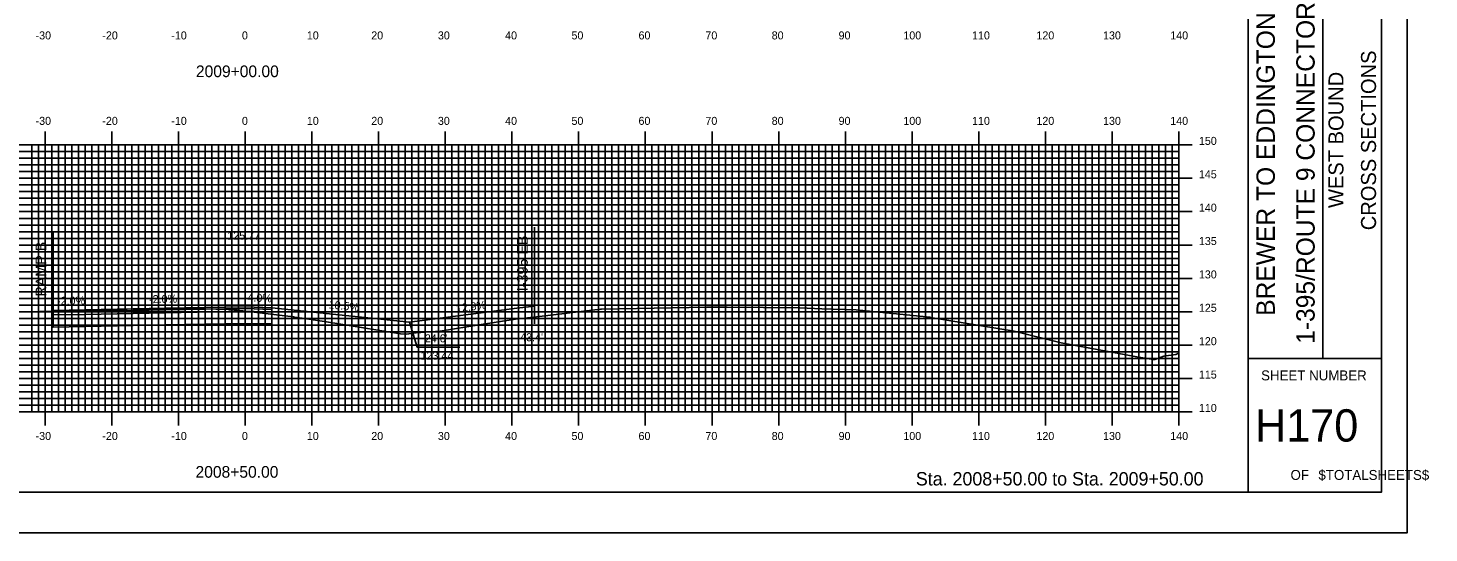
# Model space of a CAD drawing. Extents: x 853107 to 853450, y 366605 to 366825.
# Drawn here: x 853239.9 to 853450, y 366604.9 to 366680.6 of the extents above; entities that cross this region are included whole.
import ezdxf

# ---------------------------------------------------------------- set-up
doc = ezdxf.new("R2010")
doc.units = 0
for name, color, linetype in [('ANNOTATION', 7, 'Continuous'), ('BORDER', 7, 'Continuous'), ('D_Drainage_Underdrain', 7, 'Continuous'), ('D_Roadway_Centerline', 7, 'Continuous'), ('D_Roadway_Centerline_Text', 7, 'Continuous'), ('D_Roadway_Edge_Shoulder', 7, 'Continuous'), ('D_Roadway_Edge_TW', 7, 'Continuous'), ('D_Roadway_Pavement', 7, 'Continuous'), ('D_Roadway_SubGrade', 7, 'Continuous'), ('D_Text_Standard', 7, 'Continuous'), ('H_V ANNOTATION', 7, 'Continuous'), ('JUNK', 7, 'Continuous'), ('M_Roadway_Centerline', 7, 'Continuous'), ('MAJOR', 7, 'Continuous'), ('MINOR', 7, 'Continuous'), ('PLOT BOUNDARY', 7, 'Continuous'), ('S_Roadway_Centerline', 7, 'Continuous')]:
    doc.layers.add(name, color=color, linetype=linetype)

msp = doc.modelspace()

# ---------------------------------------------------------------- linework, layer by layer
at = {"layer": 'ANNOTATION'}
msp.add_lwpolyline([(853304.67, 366632.77), (853298.27, 366632.77), (853297.13, 366636.5)], dxfattribs=at)
at = {"layer": 'BORDER'}
for p, q in [((853422.9, 366611.06), (853422.9, 366821.06)), ((853434.09, 366631.06), (853434.09, 366701.06)), ((853422.9, 366631.06), (853442.9, 366631.06))]:
    msp.add_line(p, q, dxfattribs=at)
msp.add_lwpolyline([(853122.9, 366611.06), (853442.9, 366611.06), (853442.9, 366821.06), (853122.9, 366821.06)], close=True, dxfattribs=at)
at = {"layer": 'D_Drainage_Underdrain'}
msp.add_lwpolyline([(853243.7, 366638.25), (853243.7, 366635.75), (853248.5, 366635.85)], dxfattribs=at)
at = {"layer": 'D_Roadway_Centerline'}
for points in [[(853243.7, 366638.25), (853243.7, 366638.25), (853246.71, 366638.31), (853248.5, 366638.35), (853248.5, 366638.35), (853248.51, 366638.35), (853260.5, 366638.59), (853272.5, 366638.83), (853276.5, 366638.67), (853276.5, 366638.67), (853297.12, 366636.5), (853297.13, 366636.5)], [(853276.5, 366638.67), (853297.13, 366636.5)], [(853297.13, 366636.5), (853313.26, 366638.59), (853315.88, 366638.93)]]:
    msp.add_lwpolyline(points, dxfattribs=at)
at = {"layer": 'D_Roadway_Edge_Shoulder'}
msp.add_lwpolyline([(853272.5, 366638.83), (853276.5, 366638.67), (853276.5, 366638.42), (853272.5, 366638.58)], close=True, dxfattribs=at)
at = {"layer": 'D_Roadway_Edge_TW'}
for points in [[(853272.5, 366638.83), (853260.5, 366638.59), (853260.5, 366638.34), (853272.5, 366638.58)], [(853248.5, 366638.35), (853243.7, 366638.25), (853243.7, 366638), (853248.5, 366638.1)], [(853260.5, 366638.59), (853248.5, 366638.35), (853248.5, 366638.1), (853260.5, 366638.34)]]:
    msp.add_lwpolyline(points, close=True, dxfattribs=at)
at = {"layer": 'D_Roadway_Pavement'}
for points in [[(853248.5, 366638.1), (853243.7, 366638), (853243.7, 366637.59), (853248.5, 366637.68)], [(853260.5, 366638.34), (853248.5, 366638.1), (853248.5, 366637.68), (853260.5, 366637.92)], [(853272.5, 366638.58), (853260.5, 366638.34), (853260.5, 366637.92), (853272.5, 366638.16)], [(853272.5, 366638.58), (853276.5, 366638.42), (853276.5, 366638), (853272.5, 366638.16)]]:
    msp.add_lwpolyline(points, close=True, dxfattribs=at)
msp.add_lwpolyline([(853260.5, 366638.34), (853260.5, 366637.92)], dxfattribs=at)
at = {"layer": 'D_Roadway_SubGrade'}
for p, q in [((853243.7, 366650.06), (853243.7, 366635.75)), ((853315.88, 366650.73), (853315.88, 366638.93))]:
    msp.add_line(p, q, dxfattribs=at)
for points in [[(853272.5, 366638.16), (853276.5, 366638), (853276.5, 366638.42), (853276.5, 366638.67), (853276.5, 366636.25), (853272.5, 366636.33)], [(853248.5, 366637.68), (853243.7, 366637.59), (853243.7, 366637.59), (853243.7, 366635.75), (853248.5, 366635.85)], [(853260.5, 366637.92), (853248.5, 366637.68), (853248.5, 366635.85), (853260.5, 366636.09)], [(853272.5, 366638.16), (853260.5, 366637.92), (853260.5, 366636.09), (853272.5, 366636.33)]]:
    msp.add_lwpolyline(points, close=True, dxfattribs=at)
at = {"layer": 'JUNK'}
msp.add_line((853315.88, 366638.93), (853315.88, 366636.25), dxfattribs=at)
at = {"layer": 'MAJOR'}
for p, q in [((853242.5, 366665.06), (853242.5, 366663.06)), ((853252.5, 366665.06), (853252.5, 366663.06)), ((853262.5, 366665.06), (853262.5, 366663.06)), ((853272.5, 366665.06), (853272.5, 366663.06)), ((853282.5, 366665.06), (853282.5, 366663.06)), ((853292.5, 366665.06), (853292.5, 366663.06)), ((853302.5, 366665.06), (853302.5, 366663.06)), ((853312.5, 366665.06), (853312.5, 366663.06)), ((853322.5, 366665.06), (853322.5, 366663.06)), ((853332.5, 366665.06), (853332.5, 366663.06)), ((853342.5, 366665.06), (853342.5, 366663.06)), ((853352.5, 366665.06), (853352.5, 366663.06)), ((853362.5, 366665.06), (853362.5, 366663.06)), ((853372.5, 366665.06), (853372.5, 366663.06)), ((853382.5, 366665.06), (853382.5, 366663.06)), ((853392.5, 366665.06), (853392.5, 366663.06)), ((853402.5, 366665.06), (853402.5, 366663.06)), ((853412.5, 366665.06), (853412.5, 366663.06)), ((853132.5, 366663.06), (853412.5, 366663.06)), ((853132.5, 366663.06), (853412.5, 366663.06)), ((853242.5, 366623.06), (853242.5, 366663.06)), ((853252.5, 366623.06), (853252.5, 366663.06)), ((853262.5, 366623.06), (853262.5, 366663.06)), ((853272.5, 366623.06), (853272.5, 366663.06)), ((853282.5, 366623.06), (853282.5, 366663.06)), ((853292.5, 366623.06), (853292.5, 366663.06)), ((853302.5, 366623.06), (853302.5, 366663.06)), ((853312.5, 366623.06), (853312.5, 366663.06)), ((853322.5, 366623.06), (853322.5, 366663.06)), ((853332.5, 366623.06), (853332.5, 366663.06)), ((853342.5, 366623.06), (853342.5, 366663.06)), ((853352.5, 366623.06), (853352.5, 366663.06)), ((853362.5, 366623.06), (853362.5, 366663.06)), ((853372.5, 366623.06), (853372.5, 366663.06)), ((853382.5, 366623.06), (853382.5, 366663.06)), ((853392.5, 366623.06), (853392.5, 366663.06)), ((853402.5, 366623.06), (853402.5, 366663.06)), ((853414.51, 366663.06), (853410.5, 366663.06)), ((853412.5, 366623.06), (853412.5, 366663.06)), ((853412.5, 366623.06), (853412.5, 366663.06)), ((853132.5, 366658.06), (853412.5, 366658.06)), ((853414.51, 366658.06), (853410.5, 366658.06)), ((853132.5, 366653.06), (853412.5, 366653.06)), ((853414.51, 366653.06), (853410.5, 366653.06)), ((853132.5, 366648.06), (853412.5, 366648.06)), ((853414.51, 366648.06), (853410.5, 366648.06)), ((853132.5, 366643.06), (853412.5, 366643.06)), ((853414.51, 366643.06), (853410.5, 366643.06)), ((853132.5, 366638.06), (853412.5, 366638.06)), ((853414.51, 366638.06), (853410.5, 366638.06)), ((853132.5, 366633.06), (853412.5, 366633.06)), ((853414.51, 366633.06), (853410.5, 366633.06)), ((853132.5, 366628.06), (853412.5, 366628.06)), ((853414.51, 366628.06), (853410.5, 366628.06)), ((853132.5, 366623.06), (853412.5, 366623.06)), ((853132.5, 366623.06), (853412.5, 366623.06)), ((853242.5, 366621.05), (853242.5, 366623.06)), ((853252.5, 366621.05), (853252.5, 366623.06)), ((853262.5, 366621.05), (853262.5, 366623.06)), ((853272.5, 366621.05), (853272.5, 366623.06)), ((853282.5, 366621.05), (853282.5, 366623.06)), ((853292.5, 366621.05), (853292.5, 366623.06)), ((853302.5, 366621.05), (853302.5, 366623.06)), ((853312.5, 366621.05), (853312.5, 366623.06)), ((853322.5, 366621.05), (853322.5, 366623.06)), ((853332.5, 366621.05), (853332.5, 366623.06)), ((853342.5, 366621.05), (853342.5, 366623.06)), ((853352.5, 366621.05), (853352.5, 366623.06)), ((853362.5, 366621.05), (853362.5, 366623.06)), ((853372.5, 366621.05), (853372.5, 366623.06)), ((853382.5, 366621.05), (853382.5, 366623.06)), ((853392.5, 366621.05), (853392.5, 366623.06)), ((853402.5, 366621.05), (853402.5, 366623.06)), ((853414.51, 366623.06), (853410.5, 366623.06)), ((853412.5, 366621.05), (853412.5, 366623.06))]:
    msp.add_line(p, q, dxfattribs=at)
at = {"layer": 'MINOR'}
for p, q in [((853132.5, 366662.06), (853412.5, 366662.06)), ((853240.5, 366623.06), (853240.5, 366663.06)), ((853241.5, 366623.06), (853241.5, 366663.06)), ((853243.5, 366623.06), (853243.5, 366663.06)), ((853244.5, 366623.06), (853244.5, 366663.06)), ((853245.5, 366623.06), (853245.5, 366663.06)), ((853246.5, 366623.06), (853246.5, 366663.06)), ((853247.5, 366623.06), (853247.5, 366663.06)), ((853248.5, 366623.06), (853248.5, 366663.06)), ((853249.5, 366623.06), (853249.5, 366663.06)), ((853250.5, 366623.06), (853250.5, 366663.06)), ((853251.5, 366623.06), (853251.5, 366663.06)), ((853253.5, 366623.06), (853253.5, 366663.06)), ((853254.5, 366623.06), (853254.5, 366663.06)), ((853255.5, 366623.06), (853255.5, 366663.06)), ((853256.5, 366623.06), (853256.5, 366663.06)), ((853257.5, 366623.06), (853257.5, 366663.06)), ((853258.5, 366623.06), (853258.5, 366663.06)), ((853259.5, 366623.06), (853259.5, 366663.06)), ((853260.5, 366623.06), (853260.5, 366663.06)), ((853261.5, 366623.06), (853261.5, 366663.06)), ((853263.5, 366623.06), (853263.5, 366663.06)), ((853264.5, 366623.06), (853264.5, 366663.06)), ((853265.5, 366623.06), (853265.5, 366663.06)), ((853266.5, 366623.06), (853266.5, 366663.06)), ((853267.5, 366623.06), (853267.5, 366663.06)), ((853268.5, 366623.06), (853268.5, 366663.06)), ((853269.5, 366623.06), (853269.5, 366663.06)), ((853270.5, 366623.06), (853270.5, 366663.06)), ((853271.5, 366623.06), (853271.5, 366663.06)), ((853273.5, 366623.06), (853273.5, 366663.06)), ((853274.5, 366623.06), (853274.5, 366663.06)), ((853275.5, 366623.06), (853275.5, 366663.06)), ((853276.5, 366623.06), (853276.5, 366663.06)), ((853277.5, 366623.06), (853277.5, 366663.06)), ((853278.5, 366623.06), (853278.5, 366663.06)), ((853279.5, 366623.06), (853279.5, 366663.06)), ((853280.5, 366623.06), (853280.5, 366663.06)), ((853281.5, 366623.06), (853281.5, 366663.06)), ((853283.5, 366623.06), (853283.5, 366663.06)), ((853284.5, 366623.06), (853284.5, 366663.06)), ((853285.5, 366623.06), (853285.5, 366663.06)), ((853286.5, 366623.06), (853286.5, 366663.06)), ((853287.5, 366623.06), (853287.5, 366663.06)), ((853288.5, 366623.06), (853288.5, 366663.06)), ((853289.5, 366623.06), (853289.5, 366663.06)), ((853290.5, 366623.06), (853290.5, 366663.06)), ((853291.5, 366623.06), (853291.5, 366663.06)), ((853293.5, 366623.06), (853293.5, 366663.06)), ((853294.5, 366623.06), (853294.5, 366663.06)), ((853295.5, 366623.06), (853295.5, 366663.06)), ((853296.5, 366623.06), (853296.5, 366663.06)), ((853297.5, 366623.06), (853297.5, 366663.06)), ((853298.5, 366623.06), (853298.5, 366663.06)), ((853299.5, 366623.06), (853299.5, 366663.06)), ((853300.5, 366623.06), (853300.5, 366663.06)), ((853301.5, 366623.06), (853301.5, 366663.06)), ((853303.5, 366623.06), (853303.5, 366663.06)), ((853304.5, 366623.06), (853304.5, 366663.06)), ((853305.5, 366623.06), (853305.5, 366663.06)), ((853306.5, 366623.06), (853306.5, 366663.06)), ((853307.5, 366623.06), (853307.5, 366663.06)), ((853308.5, 366623.06), (853308.5, 366663.06)), ((853309.5, 366623.06), (853309.5, 366663.06)), ((853310.5, 366623.06), (853310.5, 366663.06)), ((853311.5, 366623.06), (853311.5, 366663.06)), ((853313.5, 366623.06), (853313.5, 366663.06)), ((853314.5, 366623.06), (853314.5, 366663.06)), ((853315.5, 366623.06), (853315.5, 366663.06)), ((853316.5, 366623.06), (853316.5, 366663.06)), ((853317.5, 366623.06), (853317.5, 366663.06)), ((853318.5, 366623.06), (853318.5, 366663.06)), ((853319.5, 366623.06), (853319.5, 366663.06)), ((853320.5, 366623.06), (853320.5, 366663.06)), ((853321.5, 366623.06), (853321.5, 366663.06)), ((853323.5, 366623.06), (853323.5, 366663.06)), ((853324.5, 366623.06), (853324.5, 366663.06)), ((853325.5, 366623.06), (853325.5, 366663.06)), ((853326.5, 366623.06), (853326.5, 366663.06)), ((853327.5, 366623.06), (853327.5, 366663.06)), ((853328.5, 366623.06), (853328.5, 366663.06)), ((853329.5, 366623.06), (853329.5, 366663.06)), ((853330.5, 366623.06), (853330.5, 366663.06)), ((853331.5, 366623.06), (853331.5, 366663.06)), ((853333.5, 366623.06), (853333.5, 366663.06)), ((853334.5, 366623.06), (853334.5, 366663.06)), ((853335.5, 366623.06), (853335.5, 366663.06)), ((853336.5, 366623.06), (853336.5, 366663.06)), ((853337.5, 366623.06), (853337.5, 366663.06)), ((853338.5, 366623.06), (853338.5, 366663.06)), ((853339.5, 366623.06), (853339.5, 366663.06)), ((853340.5, 366623.06), (853340.5, 366663.06)), ((853341.5, 366623.06), (853341.5, 366663.06)), ((853343.5, 366623.06), (853343.5, 366663.06)), ((853344.5, 366623.06), (853344.5, 366663.06)), ((853345.5, 366623.06), (853345.5, 366663.06)), ((853346.5, 366623.06), (853346.5, 366663.06)), ((853347.5, 366623.06), (853347.5, 366663.06)), ((853348.5, 366623.06), (853348.5, 366663.06)), ((853349.5, 366623.06), (853349.5, 366663.06)), ((853350.5, 366623.06), (853350.5, 366663.06)), ((853351.5, 366623.06), (853351.5, 366663.06)), ((853353.5, 366623.06), (853353.5, 366663.06)), ((853354.5, 366623.06), (853354.5, 366663.06)), ((853355.5, 366623.06), (853355.5, 366663.06)), ((853356.5, 366623.06), (853356.5, 366663.06)), ((853357.5, 366623.06), (853357.5, 366663.06)), ((853358.5, 366623.06), (853358.5, 366663.06)), ((853359.5, 366623.06), (853359.5, 366663.06)), ((853360.5, 366623.06), (853360.5, 366663.06)), ((853361.5, 366623.06), (853361.5, 366663.06)), ((853363.5, 366623.06), (853363.5, 366663.06)), ((853364.5, 366623.06), (853364.5, 366663.06)), ((853365.5, 366623.06), (853365.5, 366663.06)), ((853366.5, 366623.06), (853366.5, 366663.06)), ((853367.5, 366623.06), (853367.5, 366663.06)), ((853368.5, 366623.06), (853368.5, 366663.06)), ((853369.5, 366623.06), (853369.5, 366663.06)), ((853370.5, 366623.06), (853370.5, 366663.06)), ((853371.5, 366623.06), (853371.5, 366663.06)), ((853373.5, 366623.06), (853373.5, 366663.06)), ((853374.5, 366623.06), (853374.5, 366663.06)), ((853375.5, 366623.06), (853375.5, 366663.06)), ((853376.5, 366623.06), (853376.5, 366663.06)), ((853377.5, 366623.06), (853377.5, 366663.06)), ((853378.5, 366623.06), (853378.5, 366663.06)), ((853379.5, 366623.06), (853379.5, 366663.06)), ((853380.5, 366623.06), (853380.5, 366663.06)), ((853381.5, 366623.06), (853381.5, 366663.06)), ((853383.5, 366623.06), (853383.5, 366663.06)), ((853384.5, 366623.06), (853384.5, 366663.06)), ((853385.5, 366623.06), (853385.5, 366663.06)), ((853386.5, 366623.06), (853386.5, 366663.06)), ((853387.5, 366623.06), (853387.5, 366663.06)), ((853388.5, 366623.06), (853388.5, 366663.06)), ((853389.5, 366623.06), (853389.5, 366663.06)), ((853390.5, 366623.06), (853390.5, 366663.06)), ((853391.5, 366623.06), (853391.5, 366663.06)), ((853393.5, 366623.06), (853393.5, 366663.06)), ((853394.5, 366623.06), (853394.5, 366663.06)), ((853395.5, 366623.06), (853395.5, 366663.06)), ((853396.5, 366623.06), (853396.5, 366663.06)), ((853397.5, 366623.06), (853397.5, 366663.06)), ((853398.5, 366623.06), (853398.5, 366663.06)), ((853399.5, 366623.06), (853399.5, 366663.06)), ((853400.5, 366623.06), (853400.5, 366663.06)), ((853401.5, 366623.06), (853401.5, 366663.06)), ((853403.5, 366623.06), (853403.5, 366663.06)), ((853404.5, 366623.06), (853404.5, 366663.06)), ((853405.5, 366623.06), (853405.5, 366663.06)), ((853406.5, 366623.06), (853406.5, 366663.06)), ((853407.5, 366623.06), (853407.5, 366663.06)), ((853408.5, 366623.06), (853408.5, 366663.06)), ((853409.5, 366623.06), (853409.5, 366663.06)), ((853410.5, 366623.06), (853410.5, 366663.06)), ((853412.5, 366662.06), (853410.5, 366662.06)), ((853411.5, 366623.06), (853411.5, 366663.06)), ((853132.5, 366661.06), (853412.5, 366661.06)), ((853132.5, 366660.06), (853412.5, 366660.06)), ((853412.5, 366661.06), (853410.5, 366661.06)), ((853412.5, 366660.06), (853410.5, 366660.06)), ((853132.5, 366659.06), (853412.5, 366659.06)), ((853412.5, 366659.06), (853410.5, 366659.06)), ((853132.5, 366657.06), (853412.5, 366657.06)), ((853132.5, 366656.06), (853412.5, 366656.06)), ((853412.5, 366657.06), (853410.5, 366657.06)), ((853412.5, 366656.06), (853410.5, 366656.06)), ((853132.5, 366655.06), (853412.5, 366655.06)), ((853132.5, 366654.06), (853412.5, 366654.06)), ((853412.5, 366655.06), (853410.5, 366655.06)), ((853412.5, 366654.06), (853410.5, 366654.06)), ((853132.5, 366652.06), (853412.5, 366652.06)), ((853412.5, 366652.06), (853410.5, 366652.06)), ((853132.5, 366651.06), (853412.5, 366651.06)), ((853132.5, 366650.06), (853412.5, 366650.06)), ((853412.5, 366651.06), (853410.5, 366651.06)), ((853412.5, 366650.06), (853410.5, 366650.06)), ((853132.5, 366649.06), (853412.5, 366649.06)), ((853132.5, 366647.06), (853412.5, 366647.06)), ((853412.5, 366649.06), (853410.5, 366649.06)), ((853412.5, 366647.06), (853410.5, 366647.06)), ((853132.5, 366646.06), (853412.5, 366646.06)), ((853132.5, 366645.06), (853412.5, 366645.06)), ((853412.5, 366646.06), (853410.5, 366646.06)), ((853412.5, 366645.06), (853410.5, 366645.06)), ((853132.5, 366644.06), (853412.5, 366644.06)), ((853412.5, 366644.06), (853410.5, 366644.06)), ((853132.5, 366642.06), (853412.5, 366642.06)), ((853132.5, 366641.06), (853412.5, 366641.06)), ((853412.5, 366642.06), (853410.5, 366642.06)), ((853412.5, 366641.06), (853410.5, 366641.06)), ((853132.5, 366640.06), (853412.5, 366640.06)), ((853132.5, 366639.06), (853412.5, 366639.06)), ((853412.5, 366640.06), (853410.5, 366640.06)), ((853412.5, 366639.06), (853410.5, 366639.06)), ((853132.5, 366637.06), (853412.5, 366637.06)), ((853412.5, 366637.06), (853410.5, 366637.06)), ((853132.5, 366636.06), (853412.5, 366636.06)), ((853132.5, 366635.06), (853412.5, 366635.06)), ((853412.5, 366636.06), (853410.5, 366636.06)), ((853412.5, 366635.06), (853410.5, 366635.06)), ((853132.5, 366634.06), (853412.5, 366634.06)), ((853412.5, 366634.06), (853410.5, 366634.06)), ((853132.5, 366632.06), (853412.5, 366632.06)), ((853132.5, 366631.06), (853412.5, 366631.06)), ((853412.5, 366632.06), (853410.5, 366632.06)), ((853412.5, 366631.06), (853410.5, 366631.06)), ((853132.5, 366630.06), (853412.5, 366630.06)), ((853132.5, 366629.06), (853412.5, 366629.06)), ((853412.5, 366630.06), (853410.5, 366630.06)), ((853412.5, 366629.06), (853410.5, 366629.06)), ((853132.5, 366627.06), (853412.5, 366627.06)), ((853132.5, 366626.06), (853412.5, 366626.06)), ((853412.5, 366627.06), (853410.5, 366627.06)), ((853412.5, 366626.06), (853410.5, 366626.06)), ((853132.5, 366625.06), (853412.5, 366625.06)), ((853132.5, 366624.06), (853412.5, 366624.06)), ((853412.5, 366625.06), (853410.5, 366625.06)), ((853412.5, 366624.06), (853410.5, 366624.06))]:
    msp.add_line(p, q, dxfattribs=at)
at = {"layer": 'PLOT BOUNDARY'}
msp.add_lwpolyline([(853106.72, 366604.94), (853446.72, 366604.94), (853446.72, 366824.94), (853106.72, 366824.94)], close=True, dxfattribs=at)
at = {"layer": 'S_Roadway_Centerline'}
msp.add_lwpolyline([(853230.24, 366637.86), (853241.74, 366638.1), (853242.2, 366638.11), (853253.25, 366638.41), (853254.08, 366638.44), (853254.25, 366638.44), (853254.81, 366638.45), (853260.66, 366638.51), (853266.23, 366638.53), (853269.97, 366638.4), (853270.45, 366638.4), (853279.75, 366637.29), (853279.9, 366637.27), (853281.05, 366637.09), (853284.68, 366636.56), (853295.78, 366634.77), (853296.71, 366634.72), (853298.14, 366634.9), (853301.76, 366635.15), (853307.87, 366636.15), (853313.06, 366636.96), (853316.62, 366637.36), (853325.78, 366638.44), (853325.79, 366638.44), (853325.91, 366638.44), (853336.48, 366638.66), (853341.72, 366638.75), (853342.88, 366638.77), (853343.23, 366638.77), (853343.37, 366638.77), (853344.77, 366638.75), (853355.65, 366638.65), (853358.95, 366638.52), (853364.11, 366638.37), (853364.61, 366638.29), (853375.14, 366637.24), (853375.18, 366637.24), (853375.26, 366637.22), (853387.8, 366635.16), (853394.87, 366633.39), (853406.19, 366631.32), (853408.64, 366630.94), (853408.9, 366630.93), (853410.26, 366631.43), (853412.04, 366631.65), (853412.5, 366631.85)], dxfattribs=at)

# ---------------------------------------------------------------- texts
at = {"layer": 'ANNOTATION'}
for s, height, rotation, p in [('I-395 EB', 1.6, 90, (853314.87, 366641.15)), ('RAMP B', 1.6, 90, (853242.69, 366640.35)), ('-4.0%', 1.2, 357.7093, (853272.29, 366639.64)), ('-2.0%', 1.2, 1.1564, (853244.31, 366639.08)), ('-2.0%', 1.2, 1.1458, (853258.11, 366639.34)), ('-10.5%', 1.2, 353.9929, (853284.44, 366638.65)), ('12.9%', 1.2, 7.3673, (853304.18, 366637.95)), ("24.6' ", 1.2, 360, (853299.44, 366633.49)), ('123.44', 1.2, 360, (853298.8, 366630.89))]:
    msp.add_text(s, height=height, rotation=rotation, dxfattribs=at).set_placement(p)
at = {"layer": 'BORDER'}
for s, height, p in [('1-395/ROUTE 9 CONNECTOR', 2.7557, (853432.86, 366633.26)), ('BREWER TO EDDINGTON', 2.7557, (853426.89, 366637.46)), ('CROSS SECTIONS', 2.25, (853442.06, 366650.28)), ('WEST BOUND', 2.25, (853437.18, 366653.61))]:
    msp.add_text(s, height=height, rotation=90, dxfattribs=at).set_placement(p)
for s, height, p in [('SHEET NUMBER', 1.4905, (853424.83, 366627.79)), ('H170', 4.839, (853423.93, 366618.62)), ('OF', 1.491, (853429.24, 366612.88)), ('$TOTALSHEETS$', 1.4905, (853433.42, 366612.88))]:
    msp.add_text(s, height=height, dxfattribs=at).set_placement(p)
at = {"layer": 'D_Roadway_Centerline_Text'}
msp.add_text('125.77', height=1.2, dxfattribs=at).set_placement((853269.83, 366648.86))
at = {"layer": 'D_Text_Standard'}
msp.add_text("43.4'", height=1.2, dxfattribs=at).set_placement((853313.74, 366633.65))
at = {"layer": 'H_V ANNOTATION'}
for s, height, p in [('-30', 1.2, (853241.08, 366678.86)), ('-20', 1.2, (853251.09, 366678.86)), ('-10', 1.2, (853261.43, 366678.86)), ('0', 1.2, (853272.02, 366678.86)), ('10', 1.2, (853281.75, 366678.86)), ('20', 1.2, (853291.41, 366678.86)), ('30', 1.2, (853301.4, 366678.86)), ('40', 1.2, (853311.48, 366678.86)), ('50', 1.2, (853321.43, 366678.86)), ('60', 1.2, (853331.48, 366678.86)), ('70', 1.2, (853341.51, 366678.86)), ('80', 1.2, (853351.45, 366678.86)), ('90', 1.2, (853361.48, 366678.86)), ('100', 1.2, (853371.19, 366678.86)), ('110', 1.2, (853381.49, 366678.86)), ('120', 1.2, (853391.14, 366678.86)), ('130', 1.2, (853401.13, 366678.86)), ('140', 1.2, (853411.21, 366678.86)), ('2009+00.00', 1.75, (853265.12, 366673.21)), ('-30', 1.2, (853241.08, 366666.06)), ('-20', 1.2, (853251.09, 366666.06)), ('-10', 1.2, (853261.43, 366666.06)), ('0', 1.2, (853272.02, 366666.06)), ('10', 1.2, (853281.75, 366666.06)), ('20', 1.2, (853291.41, 366666.06)), ('30', 1.2, (853301.4, 366666.06)), ('40', 1.2, (853311.48, 366666.06)), ('50', 1.2, (853321.43, 366666.06)), ('60', 1.2, (853331.48, 366666.06)), ('70', 1.2, (853341.51, 366666.06)), ('80', 1.2, (853351.45, 366666.06)), ('90', 1.2, (853361.48, 366666.06)), ('100', 1.2, (853371.19, 366666.06)), ('110', 1.2, (853381.49, 366666.06)), ('120', 1.2, (853391.14, 366666.06)), ('130', 1.2, (853401.13, 366666.06)), ('140', 1.2, (853411.21, 366666.06)), ('150', 1.2, (853415.5, 366663.06)), ('145', 1.2, (853415.5, 366658.06)), ('140', 1.2, (853415.5, 366653.06)), ('135', 1.2, (853415.5, 366648.06)), ('130', 1.2, (853415.5, 366643.06)), ('125', 1.2, (853415.5, 366638.06)), ('120', 1.2, (853415.5, 366633.06)), ('115', 1.2, (853415.5, 366628.06)), ('110', 1.2, (853415.5, 366623.06)), ('-30', 1.2, (853241.08, 366618.86)), ('-20', 1.2, (853251.09, 366618.86)), ('-10', 1.2, (853261.43, 366618.86)), ('0', 1.2, (853272.02, 366618.86)), ('10', 1.2, (853281.75, 366618.86)), ('20', 1.2, (853291.41, 366618.86)), ('30', 1.2, (853301.4, 366618.86)), ('40', 1.2, (853311.48, 366618.86)), ('50', 1.2, (853321.43, 366618.86)), ('60', 1.2, (853331.48, 366618.86)), ('70', 1.2, (853341.51, 366618.86)), ('80', 1.2, (853351.45, 366618.86)), ('90', 1.2, (853361.48, 366618.86)), ('100', 1.2, (853371.19, 366618.86)), ('110', 1.2, (853381.49, 366618.86)), ('120', 1.2, (853391.14, 366618.86)), ('130', 1.2, (853401.13, 366618.86)), ('140', 1.2, (853411.21, 366618.86)), ('2008+50.00', 1.75, (853265.06, 366613.21)), ('Sta. 2008+50.00 to Sta. 2009+50.00', 2.0004, (853373.06, 366612.05))]:
    msp.add_text(s, height=height, dxfattribs=at).set_placement(p)
at = {"layer": 'M_Roadway_Centerline'}
for s, p in [('C', (853343.23, 366638.77)), ('L', (853343.23, 366638.76)), ('C', (853254.24, 366638.44)), ('L', (853254.25, 366638.44))]:
    msp.add_text(s, height=0.0146, dxfattribs=at).set_placement(p)

doc.saveas('drawing.dxf')
